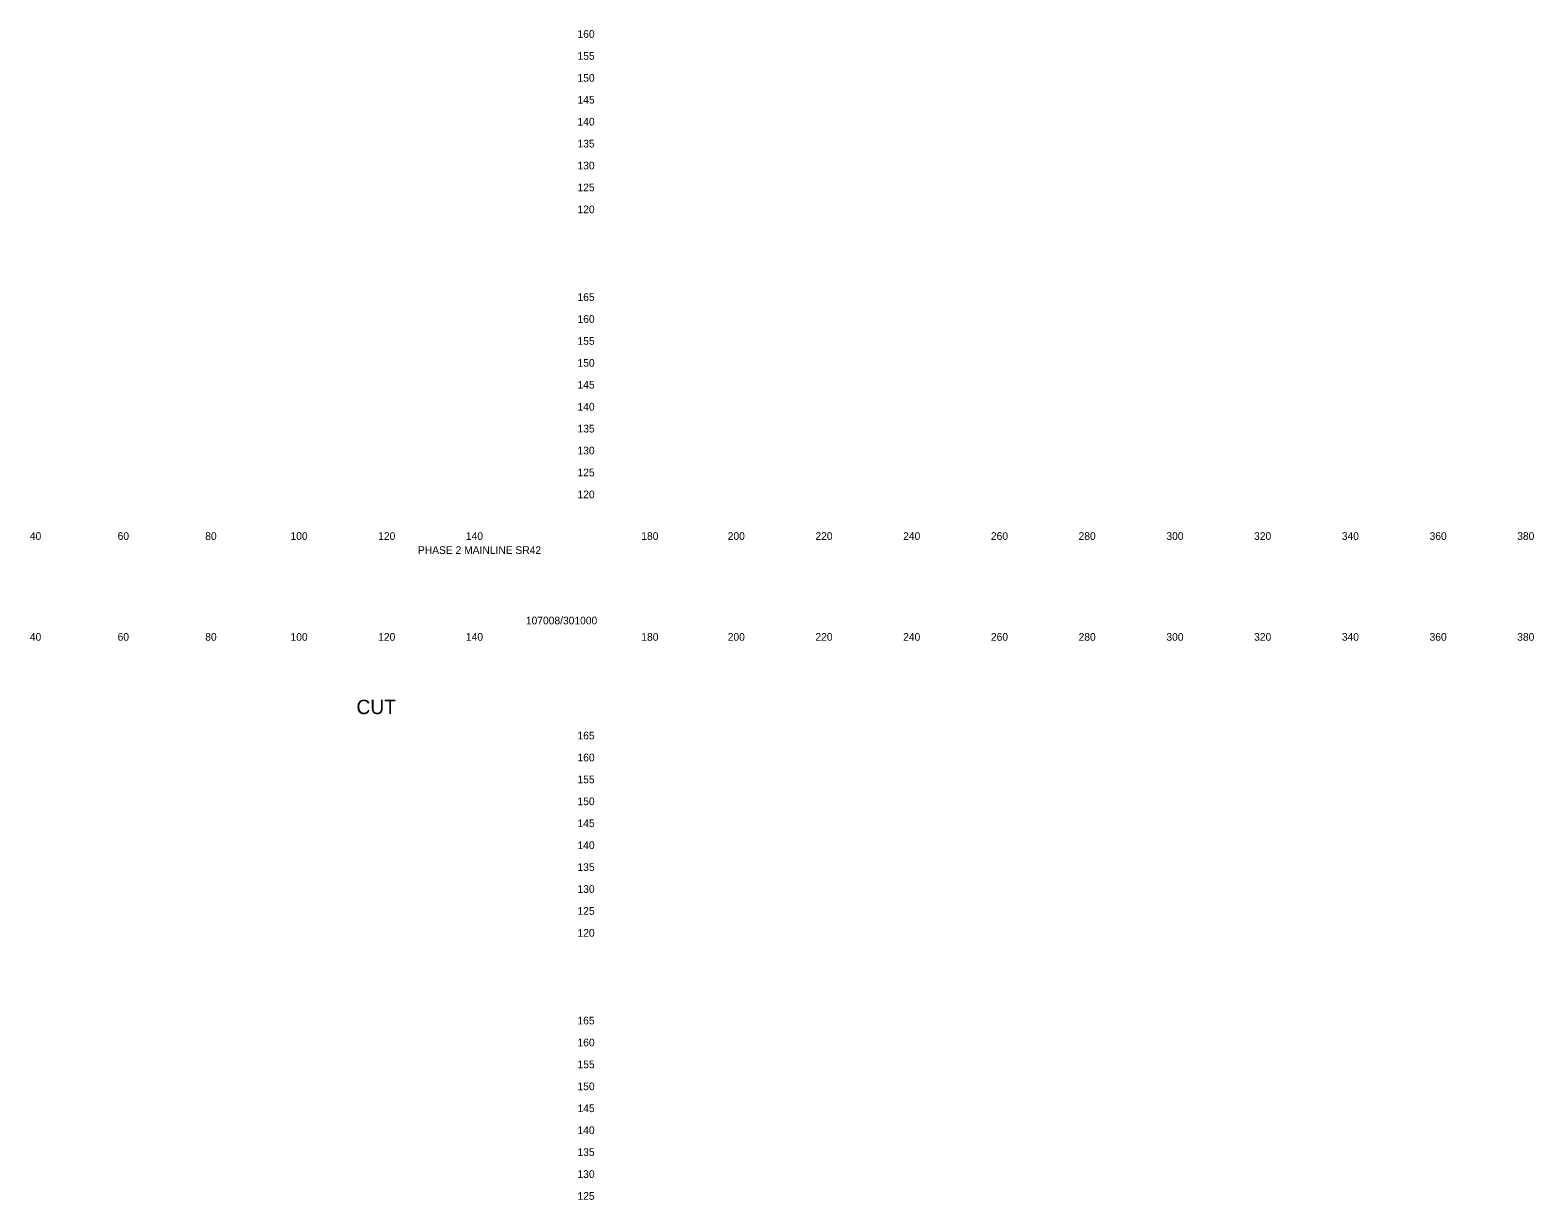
# Model space of a CAD drawing. Extents: x 21281 to 22024, y 6472 to 15208.
# Drawn here: x 21681.3 to 22024.2, y 7014.8 to 7281.6 of the extents above; entities that cross this region are included whole.
import ezdxf

# ---------------------------------------------------------------- set-up
doc = ezdxf.new("R2010")
doc.units = 0
doc.layers.add('XS_SHEET_LABELS_ELEVATION', color=7, linetype='Continuous')
doc.layers.add('XS_SHEET_LABELS_OFFSET', color=7, linetype='Continuous')

msp = doc.modelspace()

# ---------------------------------------------------------------- texts
at = {"layer": 'XS_SHEET_LABELS_ELEVATION'}
for s, p in [('  160  ', (21804.84, 7279.84)), ('  155  ', (21804.84, 7274.84)), ('  150  ', (21804.84, 7269.84)), ('  145  ', (21804.84, 7264.84)), ('  140  ', (21804.84, 7259.84)), ('  135  ', (21804.84, 7254.84)), ('  130  ', (21804.84, 7249.84)), ('  125  ', (21804.84, 7244.84)), ('  120  ', (21804.84, 7239.84)), ('  165  ', (21804.84, 7219.84)), ('  160  ', (21804.84, 7214.84)), ('  155  ', (21804.84, 7209.84)), ('  150  ', (21804.84, 7204.84)), ('  145  ', (21804.84, 7199.84)), ('  140  ', (21804.84, 7194.84)), ('  135  ', (21804.84, 7189.84)), ('  130  ', (21804.84, 7184.84)), ('  125  ', (21804.84, 7179.84)), ('  120  ', (21804.84, 7174.84)), ('  165  ', (21804.84, 7119.84)), ('  160  ', (21804.84, 7114.84)), ('  155  ', (21804.84, 7109.84)), ('  150  ', (21804.84, 7104.84)), ('  145  ', (21804.84, 7099.84)), ('  140  ', (21804.84, 7094.84)), ('  135  ', (21804.84, 7089.84)), ('  130  ', (21804.84, 7084.84)), ('  125  ', (21804.84, 7079.84)), ('  120  ', (21804.84, 7074.84)), ('  165  ', (21804.84, 7054.84)), ('  160  ', (21804.84, 7049.84)), ('  155  ', (21804.84, 7044.84)), ('  150  ', (21804.84, 7039.84)), ('  145  ', (21804.84, 7034.84)), ('  140  ', (21804.84, 7029.84)), ('  135  ', (21804.84, 7024.84)), ('  130  ', (21804.84, 7019.84)), ('  125  ', (21804.84, 7014.84))]:
    msp.add_text(s, height=1.75, dxfattribs=at).set_placement(p)
at = {"layer": 'XS_SHEET_LABELS_OFFSET'}
for s, height, p in [('  40  ', 1.75, (21679.95, 7165.34)), ('  60  ', 1.75, (21699.97, 7165.34)), ('  80  ', 1.75, (21719.95, 7165.34)), ('  100  ', 1.75, (21739.39, 7165.34)), ('  120  ', 1.75, (21759.39, 7165.34)), ('PHASE 2 MAINLINE SR42', 1.75, (21769.75, 7162.14)), ('  140  ', 1.75, (21779.39, 7165.34)), ('  180  ', 1.75, (21819.39, 7165.34)), ('  200  ', 1.75, (21839.1, 7165.34)), ('  220  ', 1.75, (21859.1, 7165.34)), ('  240  ', 1.75, (21879.1, 7165.34)), ('  260  ', 1.75, (21899.11, 7165.34)), ('  280  ', 1.75, (21919.1, 7165.34)), ('  300  ', 1.75, (21939.13, 7165.34)), ('  320  ', 1.75, (21959.13, 7165.34)), ('  340  ', 1.75, (21979.13, 7165.34)), ('  360  ', 1.75, (21999.14, 7165.34)), ('  380  ', 1.75, (22019.13, 7165.34)), ('107008/301000', 1.75, (21794.37, 7146.08)), ('  40  ', 1.75, (21679.95, 7142.34)), ('  60  ', 1.75, (21699.97, 7142.34)), ('  80  ', 1.75, (21719.95, 7142.34)), ('  100  ', 1.75, (21739.39, 7142.34)), ('  120  ', 1.75, (21759.39, 7142.34)), ('  140  ', 1.75, (21779.39, 7142.34)), ('  180  ', 1.75, (21819.39, 7142.34)), ('  200  ', 1.75, (21839.1, 7142.34)), ('  220  ', 1.75, (21859.1, 7142.34)), ('  240  ', 1.75, (21879.1, 7142.34)), ('  260  ', 1.75, (21899.11, 7142.34)), ('  280  ', 1.75, (21919.1, 7142.34)), ('  300  ', 1.75, (21939.13, 7142.34)), ('  320  ', 1.75, (21959.13, 7142.34)), ('  340  ', 1.75, (21979.13, 7142.34)), ('  360  ', 1.75, (21999.14, 7142.34)), ('  380  ', 1.75, (22019.13, 7142.34)), ('CUT', 3.273, (21755.74, 7125.61))]:
    msp.add_text(s, height=height, dxfattribs=at).set_placement(p)

doc.saveas('drawing.dxf')
